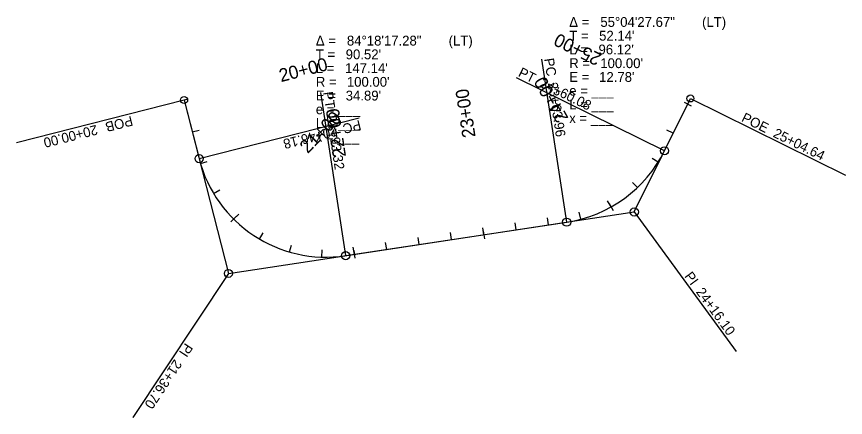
# Model space of a CAD drawing. Extents: x 21487780 to 21488412, y 8074942 to 8075249.
import ezdxf

# ---------------------------------------------------------------- set-up
doc = ezdxf.new("R2010")
doc.units = 0
for name, color, linetype in [('Contours Major', 7, 'Continuous'), ('TextAlignment', 7, 'Continuous'), ('TextAlignmentLrg', 7, 'Continuous'), ('TextAlignmentSml', 7, 'Continuous')]:
    doc.layers.add(name, color=color, linetype=linetype)

msp = doc.modelspace()

# ---------------------------------------------------------------- linework, layer by layer
at = {"layer": 'Contours Major'}
for p, q in [((21487907.64, 8075184.95), (21487919.06, 8075140.2)), ((21487907.64, 8075184.95), (21487941.45, 8075052.49)), ((21488251.21, 8075099.48), (21488294.06, 8075186.17)), ((21488274.31, 8075146.22), (21488294.06, 8075186.17)), ((21487941.45, 8075052.49), (21488251.21, 8075099.48)), ((21488030.95, 8075066.07), (21488199.66, 8075091.66))]:
    msp.add_line(p, q, dxfattribs=at)
for centre, start, end in [((21488184.66, 8075190.53), 278.62532, 333.69968), ((21488184.66, 8075190.53), 278.62532, 333.69968), ((21488015.96, 8075164.94), 194.32052, 278.62532), ((21488015.96, 8075164.94), 194.32052, 278.62532)]:
    msp.add_arc(centre, 100, start, end, dxfattribs=at)
at = {"layer": 'TextAlignment'}
for p, q in [((21488199.66, 8075091.66), (21488180.76, 8075216.23)), ((21488180.76, 8075216.23), (21488180.76, 8075216.23)), ((21488274.31, 8075146.22), (21488161.36, 8075202.05)), ((21488161.36, 8075202.05), (21488161.36, 8075202.05)), ((21488030.95, 8075066.07), (21488012.06, 8075190.64)), ((21488012.06, 8075190.64), (21488012.06, 8075190.64)), ((21487907.64, 8075184.95), (21487779.74, 8075152.3)), ((21488294.06, 8075186.17), (21488412.39, 8075127.68)), ((21487919.06, 8075140.2), (21488041.15, 8075171.37)), ((21488041.15, 8075171.37), (21488041.15, 8075171.37)), ((21487779.74, 8075152.3), (21487779.74, 8075152.3)), ((21488412.39, 8075127.68), (21488412.39, 8075127.68)), ((21488251.21, 8075099.48), (21488329.1, 8074992.91)), ((21487941.45, 8075052.49), (21487868.55, 8074942.45)), ((21488329.1, 8074992.91), (21488329.1, 8074992.91)), ((21487868.55, 8074942.45), (21487868.55, 8074942.45))]:
    msp.add_line(p, q, dxfattribs=at)
for centre, radius in [((21487907.64, 8075184.95), 2.67), ((21488294.06, 8075186.17), 2.67), ((21488274.31, 8075146.22), 3.12), ((21487919.06, 8075140.2), 3.12), ((21488251.21, 8075099.48), 3.12), ((21488199.66, 8075091.66), 3.12), ((21488030.95, 8075066.07), 3.12), ((21487941.45, 8075052.49), 3.12)]:
    msp.add_circle(centre, radius, dxfattribs=at)
at = {"layer": 'TextAlignmentLrg'}
for p, q in [((21487910.61, 8075185.7), (21487904.68, 8075184.19)), ((21488289.26, 8075183.36), (21488294.74, 8075180.65)), ((21488233.56, 8075103.3), (21488230.89, 8075108.06)), ((21487945.44, 8075094.03), (21487949.29, 8075097.9)), ((21488136.43, 8075082.07), (21488135.61, 8075087.46)), ((21488037.56, 8075067.07), (21488036.74, 8075072.47))]:
    msp.add_line(p, q, dxfattribs=at)
at = {"layer": 'TextAlignmentSml'}
for p, q in [((21487910.61, 8075185.7), (21487904.68, 8075184.19)), ((21488289.26, 8075183.36), (21488294.74, 8075180.65)), ((21487913.82, 8075160.72), (21487919.11, 8075162.08)), ((21488280.92, 8075159.59), (21488276.03, 8075162.01)), ((21488269.4, 8075137.42), (21488264.77, 8075140.32)), ((21487920.08, 8075136.52), (21487925.31, 8075138.07)), ((21488253.62, 8075118.11), (21488249.86, 8075122.06)), ((21487930.09, 8075113.68), (21487934.78, 8075116.48)), ((21488232.07, 8075105.97), (21488235.06, 8075100.63)), ((21487947.6, 8075096.2), (21487943.28, 8075091.86)), ((21488210.46, 8075093.91), (21488209.05, 8075099.19)), ((21488161.14, 8075085.82), (21488160.32, 8075091.21)), ((21488185.86, 8075089.56), (21488185.04, 8075094.96)), ((21487965.17, 8075078.79), (21487967.94, 8075083.49)), ((21488111.71, 8075078.32), (21488110.89, 8075083.71)), ((21488135.97, 8075085.09), (21488136.88, 8075079.04)), ((21488086.99, 8075074.57), (21488086.17, 8075079.97)), ((21487988.06, 8075068.9), (21487989.59, 8075074.15)), ((21488012.69, 8075064.99), (21488012.87, 8075070.45)), ((21488037.1, 8075070.09), (21488038.02, 8075064.04)), ((21488062.27, 8075070.82), (21488061.45, 8075076.22))]:
    msp.add_line(p, q, dxfattribs=at)

# ---------------------------------------------------------------- texts
at = {"layer": 'TextAlignment'}
for s, p in [('Δ = ', (21488201.58, 8075240.88)), ('55°04\'27.67"', (21488225.33, 8075240.88)), (' (LT)', (21488300.18, 8075240.88)), ('T = ', (21488201.58, 8075230.38)), ("52.14'", (21488224.39, 8075230.38)), ('Δ = ', (21488008.15, 8075226.65)), ('84°18\'17.28"', (21488031.89, 8075226.65)), (' (LT)', (21488106.75, 8075226.65)), ('T = ', (21488008.15, 8075216.15)), ("90.52'", (21488030.95, 8075216.15)), ('L = ', (21488201.58, 8075219.88)), ("96.12'", (21488223.92, 8075219.88)), ('R = ', (21488201.58, 8075209.38)), ("100.00'", (21488225.29, 8075209.38)), ('L = ', (21488008.15, 8075205.65)), ("147.14'", (21488030.49, 8075205.65)), ('E = ', (21488201.58, 8075198.88)), ("12.78'", (21488224.4, 8075198.88)), ('R = ', (21488008.15, 8075195.15)), ("100.00'", (21488031.85, 8075195.15)), ('E = ', (21488008.15, 8075184.65)), ("34.89'", (21488030.96, 8075184.65)), ('e = ___ ', (21488201.58, 8075188.38)), ('L = ___', (21488201.58, 8075177.88)), ('e = ___ ', (21488008.15, 8075174.15)), ('x = ___', (21488201.58, 8075167.38)), ('L = ___', (21488008.15, 8075163.65)), ('x = ___', (21488008.15, 8075153.15))]:
    msp.add_text(s, height=7.5, dxfattribs=at).set_placement(p)
for s, rotation, p in [('PC', 278.62532, (21488182.39, 8075216.48)), ('PT', 333.69968, (21488162.08, 8075203.52)), ('24+60.08', 333.69968, (21488178.35, 8075195.48)), ('23+63.96', 278.62532, (21488185.19, 8075198.02)), ('PT', 278.62532, (21488013.68, 8075190.89)), ('POB ', 194.32052, (21487867.35, 8075172.96)), ('21+93.32', 278.62532, (21488016.4, 8075172.95)), ('POE ', 333.69968, (21488332.44, 8075169.03)), ('20+00.00', 194.32052, (21487840.5, 8075166.11)), ('20+46.18', 194.32052, (21488023.46, 8075165.15)), ('PC', 194.32052, (21488041.55, 8075169.77)), ('25+04.64', 333.69968, (21488356.55, 8075157.12)), ('PI ', 306.1625, (21488289.15, 8075050.35)), ('24+16.10', 306.1625, (21488297.97, 8075038.29)), ('PI ', 236.47292, (21487908.55, 8074999.86)), ('21+36.70', 236.47292, (21487900.3, 8074987.4))]:
    msp.add_text(s, height=7.5, rotation=rotation, dxfattribs=at).set_placement(p)
at = {"layer": 'TextAlignmentLrg'}
for s, rotation, p in [('25+00', 153.69968, (21488226.98, 8075219.73)), ('20+00', 14.32052, (21487981.55, 8075198.64))]:
    msp.add_text(s, height=10.02, rotation=rotation, dxfattribs=at).set_placement(p)
at = {"layer": 'TextAlignmentSml'}
for s, rotation, p in [('25+00', 153.69968, (21488226.98, 8075219.73)), ('20+00', 14.32052, (21487981.55, 8075198.64)), ('24+00', 119.27509, (21488201.26, 8075171.17)), ('23+00', 98.62532, (21488130.13, 8075156.97)), ('22+00', 98.62532, (21488031.26, 8075141.97)), ('21+00', 45.15616, (21488001.88, 8075143.68))]:
    msp.add_text(s, height=10.02, rotation=rotation, dxfattribs=at).set_placement(p)

doc.saveas('drawing.dxf')
